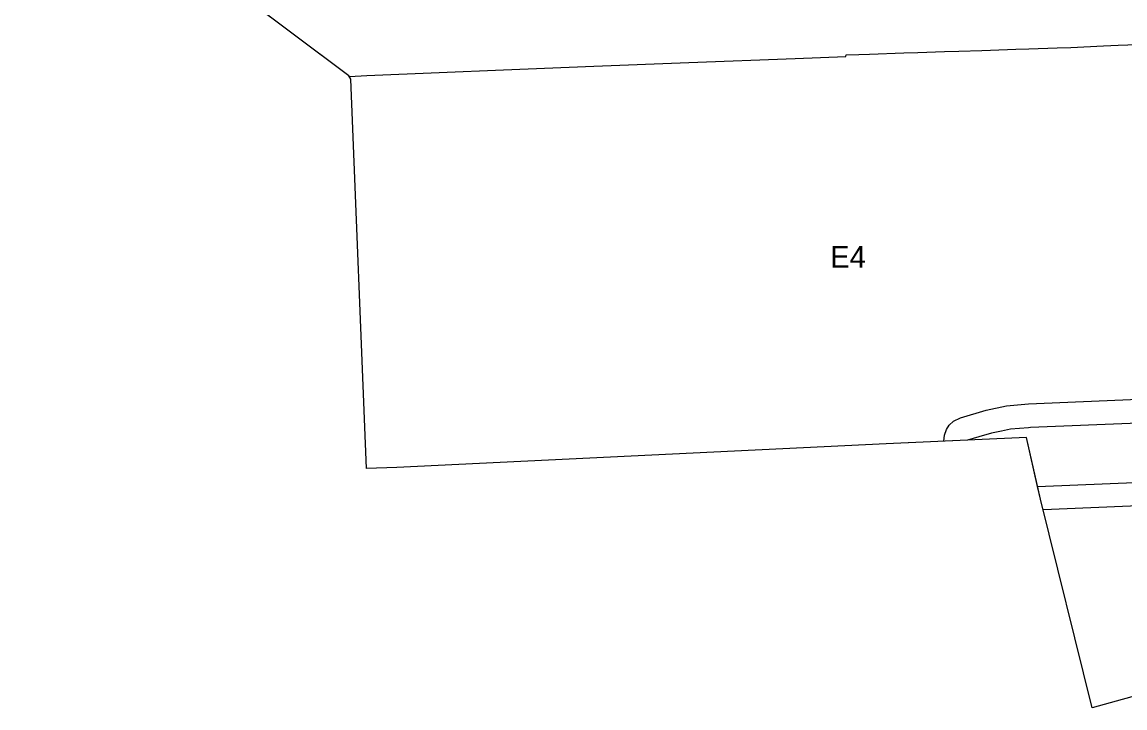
# Model space of a CAD drawing. Extents: x 7428103 to 7431580, y 5545880 to 5549002.
# Drawn here: x 7428612.9 to 7428892.8, y 5546530.7 to 5546704.9 of the extents above; entities that cross this region are included whole.
import ezdxf

# ---------------------------------------------------------------- set-up
doc = ezdxf.new("R2010")
doc.units = 0
for name, color, linetype in [('CZ_L_granica obszaru objętego planem', 7, 'Continuous'), ('CZ_L_linie rozgraniczające tereny o różnym przeznaczeniu oraz różnych warunkach ich zabudowy i zagospodarowania', 7, 'Continuous'), ('CZ_L_maksymalne nieprzekraczalne linie zabudowy', 7, 'Continuous'), ('CZ_L_opisy_linie rozgraniczające tereny o różnym przeznaczeniu oraz różnych warunkach ich zabudowy i zagospodarowania', 7, 'Continuous')]:
    doc.layers.add(name, color=color, linetype=linetype)

msp = doc.modelspace()

# ---------------------------------------------------------------- linework, layer by layer
at = {"layer": 'CZ_L_granica obszaru objętego planem'}
for p, q in [((7428695.87, 5546691.23), (7428635.63, 5546736.45)), ((7428696.37, 5546690.45), (7428695.87, 5546691.23)), ((7428700.35, 5546591.5), (7428696.37, 5546690.45)), ((7428832.23, 5546597.79), (7428708.03, 5546591.81)), ((7428867.83, 5546599.37), (7428832.23, 5546597.79)), ((7428871.36, 5546583.78), (7428867.83, 5546599.37)), ((7428708.03, 5546591.81), (7428700.35, 5546591.5)), ((7428884.44, 5546530.73), (7428871.36, 5546583.78)), ((7428916.75, 5546539.71), (7428884.44, 5546530.73))]:
    msp.add_line(p, q, dxfattribs=at)
at = {"layer": 'CZ_L_linie rozgraniczające tereny o różnym przeznaczeniu oraz różnych warunkach ich zabudowy i zagospodarowania'}
for p, q in [((7428875.63, 5546698.36), (7428879.05, 5546698.49)), ((7428879.05, 5546698.49), (7428887.31, 5546698.85)), ((7428887.31, 5546698.85), (7428891.05, 5546699.01)), ((7428891.05, 5546699.01), (7428898.31, 5546699.33)), ((7428782.08, 5546694.64), (7428809.08, 5546695.7)), ((7428809.08, 5546695.7), (7428821.99, 5546696.17)), ((7428821.99, 5546696.17), (7428822.07, 5546696.57)), ((7428822.07, 5546696.57), (7428825.27, 5546696.68)), ((7428825.27, 5546696.68), (7428827.96, 5546696.77)), ((7428827.96, 5546696.77), (7428836.69, 5546697.06)), ((7428836.69, 5546697.06), (7428840.26, 5546697.18)), ((7428840.26, 5546697.18), (7428846.98, 5546697.41)), ((7428846.98, 5546697.41), (7428850.63, 5546697.53)), ((7428850.63, 5546697.53), (7428856.46, 5546697.72)), ((7428856.46, 5546697.72), (7428858.69, 5546697.8)), ((7428858.69, 5546697.8), (7428865.12, 5546698.01)), ((7428865.12, 5546698.01), (7428868.41, 5546698.12)), ((7428868.41, 5546698.12), (7428875.63, 5546698.36)), ((7428735.05, 5546692.8), (7428758, 5546693.69)), ((7428758, 5546693.69), (7428782.08, 5546694.64)), ((7428695.96, 5546691.09), (7428700.4, 5546691.32)), ((7428700.4, 5546691.32), (7428718.76, 5546692.07)), ((7428718.76, 5546692.07), (7428735.05, 5546692.8)), ((7428858.96, 5546600.52), (7428855.7, 5546599.55)), ((7428861.44, 5546600.99), (7428858.96, 5546600.52)), ((7428863.77, 5546601.53), (7428861.44, 5546600.99)), ((7428868.32, 5546601.9), (7428863.77, 5546601.53)), ((7428868.81, 5546601.94), (7428868.32, 5546601.9)), ((7428896.25, 5546603.05), (7428868.81, 5546601.94)), ((7428855.7, 5546599.55), (7428852.84, 5546598.7)), ((7428870.63, 5546587), (7428897.25, 5546588.08))]:
    msp.add_line(p, q, dxfattribs=at)
for points in [[(7428695.96, 5546691.09), (7428695.87, 5546691.23), (7428635.63, 5546736.45), (7428633.88, 5546744.41), (7428632.29, 5546780.91), (7428631.89, 5546792.35), (7428630.63, 5546822.86), (7428629.64, 5546846.3), (7428626.74, 5546919.25), (7428614.39, 5547014.66), (7428612.91, 5547045.9), (7428612.9, 5547046.15)], [(7428852.84, 5546598.7), (7428832.23, 5546597.79), (7428708.03, 5546591.81), (7428700.35, 5546591.5), (7428696.37, 5546690.45), (7428695.96, 5546691.09)], [(7428870.63, 5546587), (7428867.83, 5546599.37), (7428852.84, 5546598.7)], [(7428943.41, 5546549.66), (7428939.45, 5546547.36), (7428932.66, 5546545.89), (7428916.75, 5546539.71), (7428884.44, 5546530.73), (7428871.36, 5546583.78), (7428870.63, 5546587)]]:
    msp.add_lwpolyline(points, dxfattribs=at)
at = {"layer": 'CZ_L_maksymalne nieprzekraczalne linie zabudowy'}
for points in [[(7428846.85, 5546598.46), (7428846.99, 5546600.01), (7428847.52, 5546601.48), (7428848.21, 5546602.52), (7428849.32, 5546603.56), (7428851.06, 5546604.43), (7428857.55, 5546606.35), (7428862.77, 5546607.44), (7428868.34, 5546607.92), (7428896.21, 5546609.11)], [(7428937.98, 5546547.1), (7428937.57, 5546548.26), (7428937.41, 5546549.41), (7428937.48, 5546550.6), (7428937.78, 5546551.73), (7428943.56, 5546567.16), (7428949.01, 5546581.13), (7428955.27, 5546594.95), (7428941.02, 5546590.86), (7428914.14, 5546584.41), (7428898.19, 5546582.13), (7428872.12, 5546581.06)]]:
    msp.add_lwpolyline(points, dxfattribs=at)

# ---------------------------------------------------------------- texts
at = {"layer": 'CZ_L_opisy_linie rozgraniczające tereny o różnym przeznaczeniu oraz różnych warunkach ich zabudowy i zagospodarowania'}
msp.add_text('E4', height=5.549, dxfattribs=at).set_placement((7428817.98, 5546642.52))

doc.saveas('drawing.dxf')
